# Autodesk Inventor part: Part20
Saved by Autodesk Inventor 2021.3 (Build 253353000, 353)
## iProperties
Created: 2022-08
Part Number: Part20
Material: Generic
Document SubType Name: Modeling
Designer: Administrator
Density: 1 g/cm^3
Appearance: Default
Author: Administrator
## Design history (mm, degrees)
feature "Encalmo Grand"
feature "Encalmo Grand (1)"
body "Solid1"
body "Solid2"
